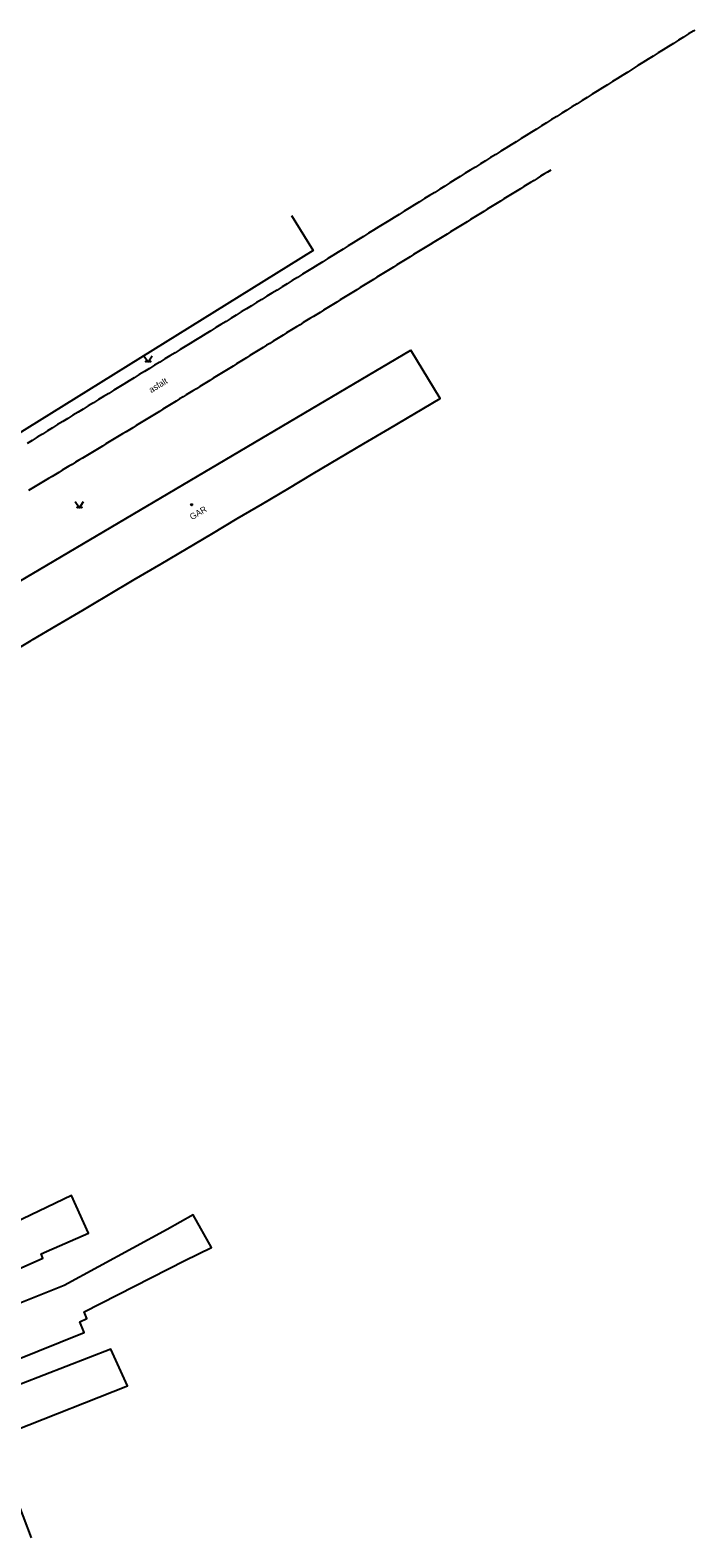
# Model space of a CAD drawing. Extents: x -545714 to -535419, y -1201788 to -1194297.
# Drawn here: x -535498.7 to -535418.6, y -1201647.9 to -1201466.3 of the extents above; entities that cross this region are included whole.
import ezdxf

# ---------------------------------------------------------------- set-up
doc = ezdxf.new("R2010")
doc.units = 0
for name, color, linetype in [('Vrstva 10', 7, 'Continuous'), ('Vrstva 11', 7, 'Continuous'), ('Vrstva 15', 7, 'Continuous'), ('Vrstva 3', 7, 'Continuous'), ('Vrstva 4', 7, 'Continuous'), ('Vrstva 5', 7, 'Continuous'), ('Vrstva 9', 7, 'Continuous')]:
    doc.layers.add(name, color=color, linetype=linetype)

msp = doc.modelspace()

# ---------------------------------------------------------------- linework, layer by layer
at = {"layer": 'Vrstva 10'}
msp.add_lwpolyline([(-535467.2, -1201488.64), (-535464.59, -1201492.87), (-535510.99, -1201521.68)], dxfattribs=at)
at = {"layer": 'Vrstva 11'}
for points in [[(-535418.63, -1201466.34), (-535418.76, -1201466.42), (-535419.38, -1201466.8), (-535419.99, -1201467.18), (-535420.6, -1201467.56), (-535421.21, -1201467.94), (-535421.82, -1201468.32), (-535422.44, -1201468.7), (-535423.05, -1201469.09), (-535423.66, -1201469.47), (-535424.27, -1201469.85), (-535424.88, -1201470.23), (-535425.49, -1201470.61), (-535426.1, -1201471), (-535426.71, -1201471.38), (-535427.32, -1201471.76), (-535427.93, -1201472.15), (-535428.54, -1201472.53), (-535429.16, -1201472.91), (-535429.77, -1201473.29), (-535430.38, -1201473.68), (-535430.99, -1201474.06), (-535431.6, -1201474.44), (-535432.21, -1201474.82), (-535432.82, -1201475.21), (-535433.43, -1201475.59), (-535434.04, -1201475.97), (-535434.65, -1201476.35), (-535435.27, -1201476.73), (-535435.88, -1201477.11), (-535436.49, -1201477.5), (-535437.1, -1201477.88), (-535437.71, -1201478.26), (-535438.32, -1201478.64), (-535438.94, -1201479.02), (-535439.55, -1201479.4), (-535440.16, -1201479.78), (-535440.77, -1201480.16), (-535441.39, -1201480.54), (-535442, -1201480.92), (-535442.61, -1201481.3), (-535443.22, -1201481.68), (-535443.83, -1201482.06), (-535444.45, -1201482.44), (-535445.06, -1201482.82), (-535445.67, -1201483.2), (-535446.28, -1201483.58), (-535446.9, -1201483.96), (-535447.51, -1201484.34), (-535448.12, -1201484.72), (-535448.73, -1201485.11), (-535449.34, -1201485.49), (-535449.96, -1201485.87), (-535450.57, -1201486.25), (-535451.18, -1201486.63), (-535451.79, -1201487), (-535452.41, -1201487.39), (-535453.02, -1201487.76), (-535453.63, -1201488.15), (-535454.24, -1201488.52), (-535454.86, -1201488.91), (-535455.47, -1201489.28), (-535456.08, -1201489.67), (-535456.69, -1201490.04), (-535457.31, -1201490.42), (-535457.92, -1201490.8), (-535458.53, -1201491.18), (-535459.14, -1201491.56), (-535459.76, -1201491.94), (-535460.37, -1201492.32), (-535460.98, -1201492.7), (-535461.6, -1201493.08), (-535462.21, -1201493.46), (-535462.82, -1201493.84), (-535463.43, -1201494.22), (-535464.05, -1201494.6), (-535464.66, -1201494.98), (-535465.27, -1201495.36), (-535465.89, -1201495.73), (-535466.5, -1201496.11), (-535467.11, -1201496.49), (-535467.73, -1201496.87), (-535468.34, -1201497.25), (-535468.95, -1201497.63), (-535469.57, -1201498.01), (-535470.18, -1201498.38), (-535470.79, -1201498.76), (-535471.41, -1201499.14), (-535472.02, -1201499.52), (-535472.63, -1201499.9), (-535473.25, -1201500.27), (-535473.86, -1201500.65), (-535474.47, -1201501.03), (-535475.09, -1201501.41), (-535475.7, -1201501.79), (-535476.32, -1201502.16), (-535476.93, -1201502.54), (-535477.54, -1201502.92), (-535478.16, -1201503.3), (-535478.77, -1201503.67), (-535479.39, -1201504.05)], [(-535435.99, -1201483.19), (-535436.39, -1201483.44), (-535436.8, -1201483.69), (-535437.2, -1201483.94), (-535437.6, -1201484.19), (-535438, -1201484.44), (-535438.41, -1201484.68), (-535438.81, -1201484.93), (-535439.21, -1201485.18), (-535439.62, -1201485.43), (-535440.02, -1201485.68), (-535440.42, -1201485.92), (-535440.82, -1201486.17), (-535441.23, -1201486.42), (-535441.63, -1201486.67), (-535442.03, -1201486.92), (-535442.43, -1201487.17), (-535442.84, -1201487.41), (-535443.24, -1201487.66), (-535443.64, -1201487.91), (-535444.04, -1201488.16), (-535444.45, -1201488.41), (-535444.85, -1201488.65), (-535445.25, -1201488.9), (-535445.65, -1201489.15), (-535446.06, -1201489.4), (-535446.46, -1201489.65), (-535446.86, -1201489.9), (-535447.26, -1201490.14), (-535447.67, -1201490.39), (-535448.07, -1201490.64), (-535448.47, -1201490.89), (-535448.87, -1201491.14), (-535449.28, -1201491.38), (-535449.68, -1201491.63), (-535450.08, -1201491.88), (-535450.49, -1201492.13), (-535450.89, -1201492.38), (-535451.29, -1201492.63), (-535451.69, -1201492.87), (-535452.1, -1201493.12), (-535452.5, -1201493.37), (-535452.9, -1201493.62), (-535453.3, -1201493.87), (-535453.7, -1201494.12), (-535454.11, -1201494.36), (-535454.51, -1201494.61), (-535454.91, -1201494.86), (-535455.31, -1201495.11), (-535455.72, -1201495.36), (-535456.12, -1201495.61), (-535456.52, -1201495.85), (-535456.93, -1201496.1), (-535457.33, -1201496.35), (-535457.73, -1201496.6), (-535458.13, -1201496.85), (-535458.54, -1201497.09), (-535458.94, -1201497.34), (-535459.34, -1201497.59), (-535459.74, -1201497.84), (-535460.15, -1201498.09), (-535460.55, -1201498.34), (-535460.95, -1201498.58), (-535461.35, -1201498.83), (-535461.76, -1201499.08), (-535462.16, -1201499.33), (-535462.56, -1201499.58), (-535462.96, -1201499.83), (-535463.37, -1201500.07), (-535463.77, -1201500.32), (-535464.17, -1201500.57), (-535464.57, -1201500.82), (-535464.98, -1201501.07), (-535465.38, -1201501.32), (-535465.78, -1201501.56), (-535466.18, -1201501.81), (-535466.59, -1201502.06), (-535466.99, -1201502.31), (-535467.39, -1201502.56), (-535467.79, -1201502.8), (-535468.2, -1201503.05), (-535468.6, -1201503.3), (-535469, -1201503.55), (-535469.4, -1201503.8), (-535469.81, -1201504.05), (-535470.21, -1201504.29), (-535470.61, -1201504.54), (-535471.02, -1201504.79), (-535471.42, -1201505.04), (-535471.82, -1201505.29), (-535472.22, -1201505.53), (-535472.63, -1201505.78), (-535473.03, -1201506.03), (-535473.43, -1201506.28), (-535473.83, -1201506.53), (-535474.24, -1201506.78), (-535474.64, -1201507.02), (-535475.04, -1201507.27), (-535475.44, -1201507.52), (-535475.85, -1201507.77), (-535476.25, -1201508.02)], [(-535479.39, -1201504.05), (-535480, -1201504.43), (-535480.62, -1201504.8), (-535481.23, -1201505.18), (-535481.85, -1201505.56), (-535482.46, -1201505.93), (-535483.07, -1201506.31), (-535483.69, -1201506.69), (-535484.3, -1201507.06), (-535484.92, -1201507.44), (-535485.53, -1201507.82), (-535486.15, -1201508.19), (-535486.76, -1201508.57), (-535487.38, -1201508.95), (-535487.99, -1201509.32), (-535488.61, -1201509.7), (-535489.22, -1201510.08), (-535489.83, -1201510.45), (-535490.45, -1201510.83), (-535491.06, -1201511.21), (-535491.68, -1201511.58), (-535492.29, -1201511.96), (-535492.91, -1201512.33), (-535493.52, -1201512.71), (-535494.14, -1201513.09), (-535494.75, -1201513.47), (-535495.37, -1201513.84), (-535495.98, -1201514.22), (-535496.59, -1201514.6), (-535497.21, -1201514.97), (-535497.82, -1201515.35), (-535498.44, -1201515.73), (-535499.05, -1201516.11)], [(-535476.25, -1201508.02), (-535476.65, -1201508.26), (-535477.05, -1201508.51), (-535477.46, -1201508.76), (-535477.86, -1201509.01), (-535478.26, -1201509.26), (-535478.66, -1201509.51), (-535479.07, -1201509.75), (-535479.47, -1201510), (-535479.87, -1201510.25), (-535480.27, -1201510.5), (-535480.68, -1201510.75), (-535481.08, -1201511), (-535481.48, -1201511.24), (-535481.89, -1201511.49), (-535482.29, -1201511.74), (-535482.69, -1201511.99), (-535483.09, -1201512.24), (-535483.5, -1201512.48), (-535483.9, -1201512.73), (-535484.3, -1201512.98), (-535484.71, -1201513.22), (-535485.11, -1201513.47), (-535485.51, -1201513.72), (-535485.92, -1201513.96), (-535486.32, -1201514.21), (-535486.73, -1201514.45), (-535487.13, -1201514.7), (-535487.54, -1201514.94), (-535487.94, -1201515.19), (-535488.34, -1201515.44), (-535488.75, -1201515.68), (-535489.15, -1201515.93), (-535489.56, -1201516.17), (-535489.96, -1201516.42), (-535490.36, -1201516.66), (-535490.77, -1201516.91), (-535491.17, -1201517.15), (-535491.58, -1201517.4), (-535491.98, -1201517.64), (-535492.39, -1201517.89), (-535492.8, -1201518.13), (-535493.2, -1201518.37), (-535493.61, -1201518.62), (-535494.01, -1201518.86), (-535494.42, -1201519.1), (-535494.82, -1201519.34), (-535495.23, -1201519.59), (-535495.64, -1201519.83), (-535496.04, -1201520.07), (-535496.45, -1201520.31), (-535496.86, -1201520.56), (-535497.26, -1201520.8), (-535497.67, -1201521.04), (-535498.07, -1201521.28), (-535498.48, -1201521.52), (-535498.89, -1201521.77)]]:
    msp.add_lwpolyline(points, dxfattribs=at)
at = {"layer": 'Vrstva 3'}
for points in [[(-535484.98, -1201505.54), (-535484.48, -1201506.29), (-535483.98, -1201505.54)], [(-535493.24, -1201523.1), (-535492.74, -1201523.85), (-535492.24, -1201523.1)]]:
    msp.add_lwpolyline(points, dxfattribs=at)
for centre in [(-535484.73, -1201506.24), (-535484.23, -1201506.24), (-535492.99, -1201523.8), (-535492.49, -1201523.8)]:
    msp.add_circle(centre, 0.05, dxfattribs=at)
at = {"layer": 'Vrstva 4'}
msp.add_lwpolyline([(-535508.66, -1201537.84), (-535452.84, -1201504.86)], dxfattribs=at)
at = {"layer": 'Vrstva 5'}
for points in [[(-535508.66, -1201537.84), (-535505.13, -1201543.65), (-535501.77, -1201541.75), (-535498.54, -1201539.84), (-535498.42, -1201539.77), (-535495.44, -1201538), (-535492.35, -1201536.17), (-535491.12, -1201535.44), (-535489.25, -1201534.34), (-535486.15, -1201532.5), (-535482.92, -1201530.59), (-535479.86, -1201528.78), (-535476.81, -1201526.97), (-535473.75, -1201525.16), (-535470.7, -1201523.36), (-535467.64, -1201521.55), (-535464.59, -1201519.74), (-535461.53, -1201517.93), (-535458.48, -1201516.12), (-535455.42, -1201514.31), (-535452.37, -1201512.51), (-535449.32, -1201510.7), (-535452.84, -1201504.86)], [(-535508.29, -1201622.96), (-535509.57, -1201619.7), (-535497.15, -1201614.22), (-535497.36, -1201613.69), (-535491.66, -1201611.18), (-535493.68, -1201606.66), (-535511.42, -1201615.11), (-535516.38, -1201617.2)], [(-535505.12, -1201631.43), (-535506.53, -1201627.98), (-535503.73, -1201626.88), (-535503.95, -1201626.32), (-535501.16, -1201625.22), (-535500.63, -1201626.56), (-535492.18, -1201623.16), (-535492.7, -1201621.86), (-535491.84, -1201621.47), (-535492.19, -1201620.68), (-535480.05, -1201614.49), (-535476.82, -1201612.92), (-535479.05, -1201608.98), (-535482.17, -1201610.77), (-535494.6, -1201617.48), (-535508.29, -1201622.96), (-535513.53, -1201625.03)], [(-535498.53, -1201647.88), (-535502.55, -1201637.28), (-535499.99, -1201636.39), (-535500.56, -1201634.94), (-535486.94, -1201629.59), (-535488.98, -1201625.15), (-535505.12, -1201631.43), (-535510.36, -1201633.56)]]:
    msp.add_lwpolyline(points, dxfattribs=at)
at = {"layer": 'Vrstva 9'}
msp.add_circle((-535479.22, -1201523.49), 0.0875, dxfattribs=at)

# ---------------------------------------------------------------- texts
at = {"layer": 'Vrstva 15'}
for s, rotation, p in [('asfalt', 31.77, (-535484.09, -1201510.05)), ('GAR', 30.73, (-535479.18, -1201525.35))]:
    msp.add_text(s, height=0.75, rotation=rotation, dxfattribs=at).set_placement(p)

doc.saveas('drawing.dxf')
